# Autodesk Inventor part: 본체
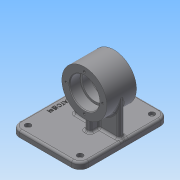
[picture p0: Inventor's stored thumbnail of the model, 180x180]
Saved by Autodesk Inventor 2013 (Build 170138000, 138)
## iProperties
Created: 2019-09
Part Number: 본체
Material: 일반
Document SubType Name: Modeling
Designer: Administrator
Density: 1 g/cm^3
Author: Administrator
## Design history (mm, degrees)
sketch "스케치1"
  geometry: C1 r 32 at (0, 0); 1 further point
  constraints: 1 centre point, 1 coincident
  dimensions: "d0" = 64 diameter of C1
extrude "돌출1" new body sketch "스케치1" stored distance "d1" = 42; taper "d2" = 0 deg
node "작업 평면1"
node "작업 평면2"
hole "구멍2" diameter "d63" = 42; stored, may be unused: countersink angle "d67" = 90 deg, drill point angle "d69" = 0 deg; dims "d64" = 6, "d65" = 8, "d66" = 4.4, "d68" = 15, "d103" = 10, "d104" = 10
hole "구멍3" diameter "d72" = 42; stored, may be unused: countersink angle "d76" = 90 deg, drill point angle "d78" = 0 deg; dims "d73" = 6, "d74" = 8, "d75" = 4.4, "d77" = 15, "d105" = 10, "d106" = 10
hole "구멍4" diameter "d81" = 36; stored, may be unused: countersink angle "d85" = 90 deg, drill point angle "d87" = 118 deg; dims "d79" = 10, "d80" = 10, "d82" = 6, "d83" = 8, "d84" = 4.4, "d86" = 15
chamfer "모따기1" distance "d88" = 1; stored, may be unused: second distance "d89" = 2, angle "d90" = 45 deg
sketch "스케치16"
  geometry: C1 r 32 at (0, 0) reference; C2 r 22 at (0, 0) reference; C3 r 26 at (0, 0); 1 further point
  constraints: 1 centre point, 1 coincident, 1 vertical alignment
  dimensions: "d91" = 52 diameter of C3; "d92" = 26 distance of C3.centre point (0, 26)
hole "구멍5" sketch "스케치16" at (0, 26) diameter "d93" = 3.242; stored, may be unused: countersink angle "d97" = 90 deg, drill point angle "d99" = 118 deg; dims "d94" = 8, "d95" = 8, "d96" = 4.4, "d98" = 10
sketch "스케치17"
  geometry: L1 (-50, 63)-(-59, 63); L2 (-59, 63)-(-59, -63); L3 (-59, -63)-(-50, -63); L4 (-50, -63)-(-50, 63); 2 further points
  constraints: 8 end point, 2 parallel, 1 horizontal, 1 horizontal alignment, 1 midpoint, 1 perpendicular
  dimensions: "d107" = 126 distance of L1.end L2.end; "d109" = 9 distance of L2.end L3.end; "d110" = 59 distance from line of L2 point (0, 0)
extrude "돌출9" join sketch "스케치17" distance "d111" = 36; taper "d113" = 0 deg; dims "d112" = 62, "d114" = 0
sketch "스케치18"
  geometry: L1 (30, 59)-(94, 59); L2 (94, 59)-(94, 67); L3 (94, 67)-(30, 67); L4 (30, 67)-(30, 59); L5 (30, 59)-(94, 67); L6 (94, 59)-(30, 67); L7 (58, 46)-(66, 46); L8 (66, 46)-(66, 80); L9 (66, 80)-(58, 80); L10 (58, 80)-(58, 46); L11 (58, 46)-(66, 80); L12 (66, 46)-(58, 80); 1 further point
  constraints: 24 end point, 4 midpoint, 4 parallel, 2 horizontal, 2 perpendicular
  dimensions: "d115" = 64 distance of L3.end L2.end; "d116" = 8 distance of L2.end L1.end; "d117" = 8 distance of L9.end L8.end; "d118" = 34 distance of L8.end L7.end
extrude "돌출10" join sketch "스케치18" stored distance "d119" = 36; taper "d120" = 0 deg
fillet "모깎기2" dims "d121" = 12
sketch "스케치19"
  geometry: A1 r 12 centre (0, 12) between (-12, 12) and (0, 0) reference; 2 further points
  constraints: 1 coincident
hole "구멍6" sketch "스케치19" at (0, 12) diameter "d122" = 4.5; stored, may be unused: countersink angle "d126" = 90 deg, drill point angle "d128" = 0 deg; dims "d123" = 8, "d124" = 8, "d125" = 4.4, "d127" = 10
sketch "스케치20"
  geometry: L1 (-12, 12)-(-12, 114) reference; L2 (0, 126)-(74, 126) reference; 2 further points
  constraints: 1 other
  dimensions: "d135" = 10 distance from line of L1 point (-2, 63); "d136" = 63 distance from line of L2 point (-2, 63)
feature "엠보싱2" sketch "스케치20" dims "d137" = 0.5, "d138" = 0
fillet "모깎기3" dims "d139" = 3
fillet "모깎기4" dims "d140" = 3
fillet "모깎기5" dims "d141" = 3
fillet "모깎기6" dims "d142" = 3
fillet "모깎기7" dims "d143" = 0.3
node "솔리드1"
pattern_circular "원형 패턴1" dims angle "d101" = 360 deg
mirror "대칭1"
pattern_linear "직사각형 패턴2" dims "d131" = 102, "d134" = 74
other parameters: "d4" = -59, "d28" = -59
